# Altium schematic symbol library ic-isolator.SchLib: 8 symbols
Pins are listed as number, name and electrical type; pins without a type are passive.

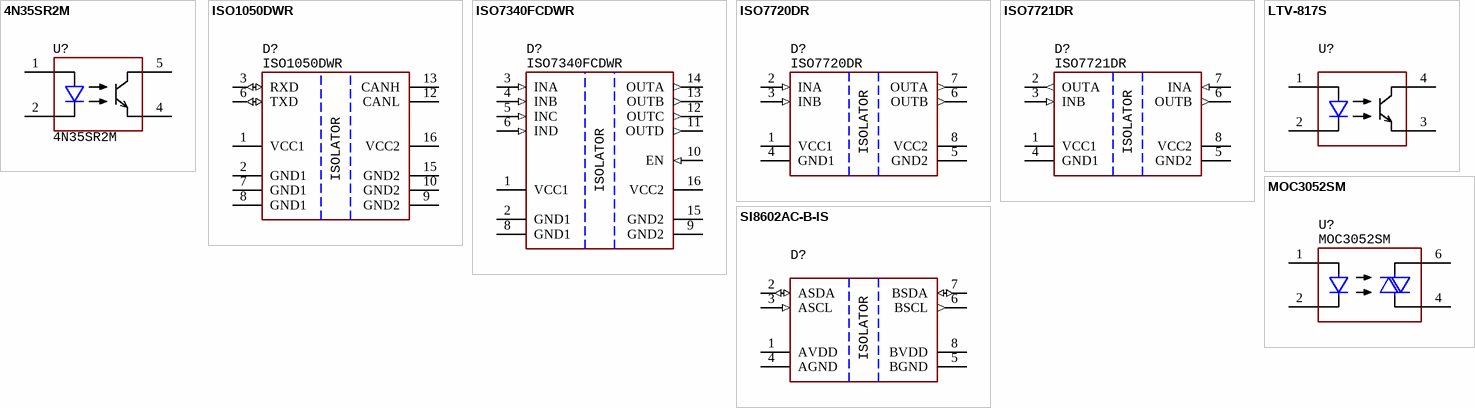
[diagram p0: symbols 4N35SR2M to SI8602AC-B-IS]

## 4N35SR2M
designator U?
NPN, 30V, 60mA led, SMD-6, -55...+150°C; Manufacturer: ON Semiconductor
footprint 6-SMD
pins: 1 A, 2 K, 4 E, 5 C

## ISO1050DWR
designator D?
CAN isolator, 1 Mb/s, supply 3...5.5V, 5000 Vrms, -55...+105°C; Manufacturer: Texas Instruments
footprint 16-TSSOP (pitch 1.27 mm)
pins: 1 VCC1, 2 GND1, 3 RXD (io), 6 TXD (io), 7 GND1, 8 GND1, 9 GND2, 10 GND2, 12 CANL, 13 CANH, 15 GND2, 16 VCC2

## ISO7340FCDWR
designator D?
Digital isolator 4/0, 25 Mb/s, 3000 Vrms, SOIC-16, 32 ns, -40...+125°C; Manufacure: Texas Instruments
footprint 16-TSSOP (pitch 1.27 mm)
pins: 1 VCC1 (power), 2 GND1 (power), 3 INA (in), 4 INB (in), 5 INC (in), 6 IND (in), 8 GND1 (power), 9 GND2 (power), 10 EN (in), 11 OUTD (out), 12 OUTC (out), 13 OUTB (out), 14 OUTA (out), 15 GND2 (power), 16 VCC2 (power)

## ISO7720DR
designator D?
Digital isolator 2/0, 100 Mb/s, 3000 Vrms, SOIC-8, 32 ns, -55...+125°C; Manufacture: Texas Instruments
footprint 8-SOIC (pitch 1.27 mm)
pins: 1 VCC1, 2 INA (in), 3 INB (in), 4 GND1, 5 GND2, 6 OUTB (out), 7 OUTA (out), 8 VCC2

## ISO7721DR
designator D?
Digital isolator 1/1, 100 Mb/s, 3000 Vrms, SOIC-8, 32 ns, -55...+125°C; Manufacture: Texas Instruments
footprint 8-SOIC (pitch 1.27 mm)
pins: 1 VCC1, 2 OUTA (out), 3 INB (in), 4 GND1, 5 GND2, 6 OUTB (out), 7 INA (in), 8 VCC2

## LTV-817S
designator U?  (value not drawn)
Optoisolator, 35V, 50 mA, 5000 Vrms, 18 us, SMD-4, 55...+125°C; Manufacturer: Lite-On
footprint 4-SMD (SOIC, 4-Leads, Body 4,60x6,50mm, Pitch 1,27mm, IPC Medium Density)
pins: 1 A, 2 C, 3 E, 4 C

## MOC3052SM
designator U?
SCR driver, 600V, 60 mA, 5250 Vrms, SMD-6, 55...+125°C; Manufacture: ON Semiconductor
footprint 6-SMD (pitch 2.54 mm)
pins: 1 A, 2 C, 4 A1, 6 A2

## SI8602AC-B-IS
designator D?  (value not drawn)
Isolator I2C, 10 Mb/s, 3750 Vrms, supply 3...5.5V, SOIC-8, 38 ns, -55...+125°C
footprint 8-SOIC (pitch 1.27 mm)
pins: 1 AVDD, 2 ASDA (io), 3 ASCL (in), 4 AGND, 5 BGND, 6 BSCL (out), 7 BSDA (io), 8 BVDD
